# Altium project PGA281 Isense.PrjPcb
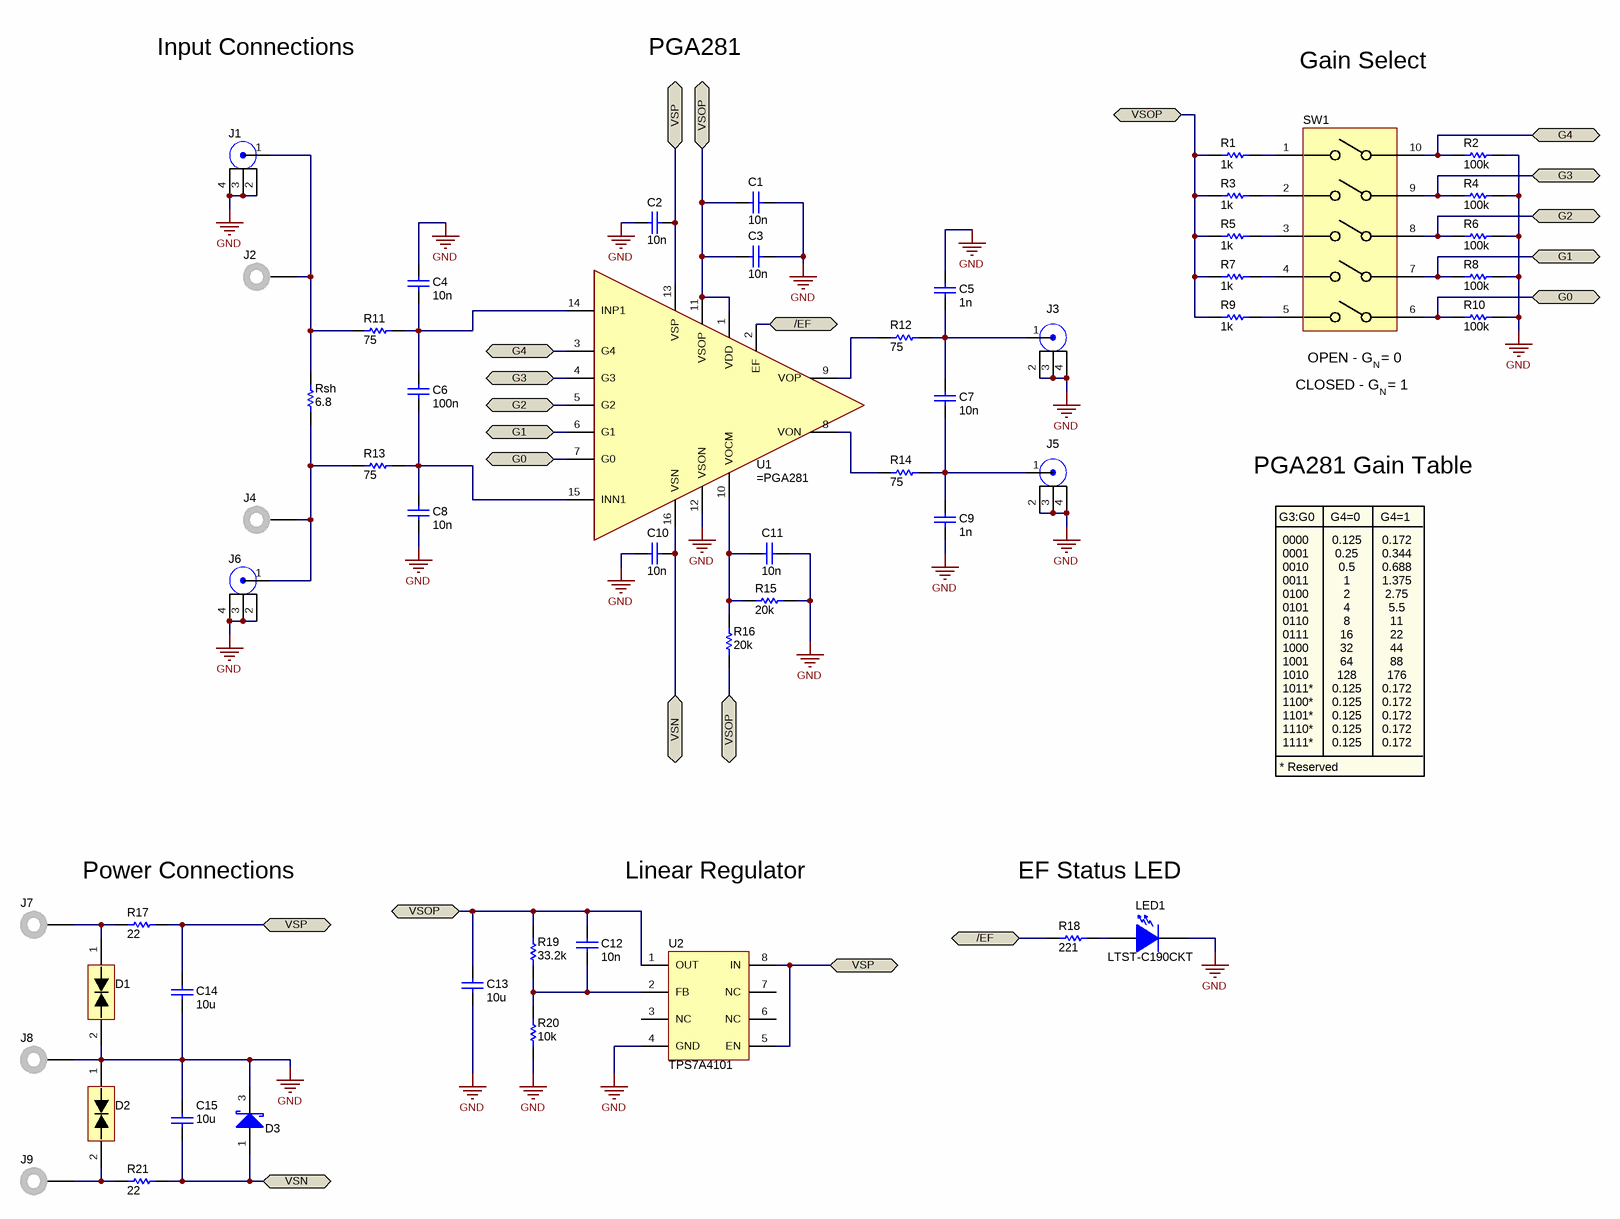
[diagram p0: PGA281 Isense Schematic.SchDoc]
CopyrightYear: 2012; PCB_Layout: Who did the Layout?; PCB_Rev: E1; PRJ_Customer: Public Release; PRJ_Engineer: Enter name of project lead; PRJ_Number: XX####; PRJ_Title: Change in menu Project|Project Options|Parameters; SCH_Rev: E1; TechSupport: http://www.ti.com/support
2 sheets, 58 parts. Net scope: flat (ports and power ports of the same name join across sheets).
Board file: PCB.PcbDoc
Sheets:
  PGA281 Isense Schematic.SchDoc
  Hardware_ANSI-B.SchDoc

## Sheet PGA281 Isense Schematic.SchDoc
size 431 x 279 mm; Date: Not shown in title block; ApprovedBy: Not shown in title block; CheckedBy: Not shown in title block; Author: Not shown in title block; CompanyName: Not shown in title block; Engineer: Not shown in title block; Organization: Not shown in title block; Address1: Not shown in title block; Address2: Not shown in title block; Address3: Not shown in title block; Address4: Not shown in title block; DocumentNumber: 1; Revision: Use project parameter SCH_Rev; SheetNumber: 1; SheetTotal: 1; PageSetup: Record=PageOptions|CenterHorizontal=True|CenterVertical=True|PrintScale=0.64|XCorrection=1.00|YCorrection=1.00|PrintKind=0|BorderSize=5000000|LeftOffset=0|BottomOffset=0|Orientation=2|PaperLength=1000|PaperWidth=1000|Scale=100|PaperSource=15|PrintQuality=600|MediaType=1|DitherType=10|PaperKind=Letter|PrintScaleMode=1

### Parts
C1  10n  [0603]
C2  10n  [0603]
C3  10n  [0603]
C4  10n  [0603]
C5  1n  [0603]
C6  100n  [0603]
C7  10n  [0603]
C8  10n  [0603]
C9  1n  [0603]
C10  10n  [0603]
C11  10n  [0603]
C12  10n  [0805]
C13  10u  [1206]
C14  10u  [1206]
C15  10u  [1206]
D1  SMBJ24CA  [SMB]  (value not drawn)
D2  SMBJ24CA  [SMB]  (value not drawn)
D3  BAS70-TP  [DBZ0003A_N]  (value not drawn)
J1  VIN+  [Right Angle BNC]  (value not drawn)
J2  I_IN+  [Johnson_108-0740-001]  (value not drawn)
J3  VOUT+  [Right Angle BNC]  (value not drawn)
J4  I_IN-  [Johnson_108-0740-001]  (value not drawn)
J5  VOUT-  [Right Angle BNC]  (value not drawn)
J6  VIN-  [Right Angle BNC]  (value not drawn)
J7  VSP  [Johnson_108-0740-001]  (value not drawn)
J8  GND  [Johnson_108-0740-001]  (value not drawn)
J9  VSN  [Johnson_108-0740-001]  (value not drawn)
LED1  LTST-C190CKT  [Diode_0603]
R1  value 1k  [0603]  (hidden comment: Used in BOM report)
R2  value 100k  [0603]  (hidden comment: Used in BOM report)
R3  value 1k  [0603]  (hidden comment: Used in BOM report)
R4  value 100k  [0603]  (hidden comment: Used in BOM report)
R5  value 1k  [0603]  (hidden comment: Used in BOM report)
R6  value 100k  [0603]  (hidden comment: Used in BOM report)
R7  value 1k  [0603]  (hidden comment: Used in BOM report)
R8  value 100k  [0603]  (hidden comment: Used in BOM report)
R9  value 1k  [0603]  (hidden comment: Used in BOM report)
R10  value 100k  [0603]  (hidden comment: Used in BOM report)
R11  value 75  [0805]  (hidden comment: Used in BOM report)
R12  value 75  [0805]  (hidden comment: Used in BOM report)
R13  value 75  [0805]  (hidden comment: Used in BOM report)
R14  value 75  [0805]  (hidden comment: Used in BOM report)
R15  value 20k  [0805]  (hidden comment: Used in BOM report)
R16  value 20k  [0805]  (hidden comment: Used in BOM report)
R17  value 22  [1206]  (hidden comment: Used in BOM report)
R18  value 221  [0805]  (hidden comment: Used in BOM report)
R19  value 33.2k  [0805]  (hidden comment: Used in BOM report)
R20  value 10k  [0805]  (hidden comment: Used in BOM report)
R21  value 22  [1206]  (hidden comment: Used in BOM report)
Rsh  value 6.8  [2512]  (hidden comment: Used in BOM report)
SW1  Used in BOM report  [A6S-5104-H]  (value not drawn)
U1  (no value)  [PW0016A_N]
U2  TPS7A4101  [dgk-8]

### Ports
/EF, G0, G1, G2, G3, G4, VSN, VSOP, VSP

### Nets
GND: C1.1 C2.2 C3.1 C4.1 C5.1 C8.2 C9.2 C10.1 C11.2 C13.2 C14.2 C15.1 D1.2 D2.1 D3.3 J1.2 J1.3 J1.4 J3.2 J3.3 J3.4 J5.2 J5.3 J5.4 J6.2 J6.3 J6.4 J8.1 LED1.2(K) R2.2 R4.2 R6.2 R8.2 R10.2 R15.1 R20.2 U1.12(VSON) U2.4(GND)
/EF: R18.1 U1.2(EF) ; port /EF
G0: R10.1 SW1.6 U1.7(G0) ; port G0
G1: R8.1 SW1.7 U1.6(G1) ; port G1
G2: R6.1 SW1.8 U1.5(G2) ; port G2
G3: R4.1 SW1.9 U1.4(G3) ; port G3
G4: R2.1 SW1.10 U1.3(G4) ; port G4
VSN: C10.2 C15.2 D3.1 R21.2 U1.16(VSN) ; port VSN
VSOP: C1.2 C3.2 C12.1 C13.1 R1.1 R3.1 R5.1 R7.1 R9.1 R16.1 R19.2 U1.1(VDD) U1.11(VSOP) U2.1(OUT) ; port VSOP
VSP: C2.1 C14.1 R17.2 U1.13(VSP) U2.5(EN) U2.8(IN) ; port VSP
NetC4_2: C4.2 C6.1 R11.2 U1.14(INP1)
NetC5_2: C5.2 C7.1 J3.1 R12.2
NetC6_2: C6.2 C8.1 R13.2 U1.15(INN1)
NetC7_2: C7.2 C9.1 J5.1 R14.2
NetC11_1: C11.1 R15.2 R16.2 U1.10(VOCM)
NetC12_2: C12.2 R19.1 R20.1 U2.2(FB)
NetD1_1: D1.1 J7.1 R17.1
NetD2_2: D2.2 J9.1 R21.1
NetJ1_1: J1.1 J2.1 R11.1 Rsh.2
NetJ4_1: J4.1 J6.1 R13.1 Rsh.1
NetLED1_1: LED1.1(A) R18.2
NetR1_2: R1.2 SW1.1
NetR3_2: R3.2 SW1.2
NetR5_2: R5.2 SW1.3
NetR7_2: R7.2 SW1.4
NetR9_2: R9.2 SW1.5
NetR12_1: R12.1 U1.9(VOP)
NetR14_1: R14.1 U1.8(VON)

Not connected (* = marked no-connect by the designer): D3 2; U2 3(NC) 6(NC) 7(NC)

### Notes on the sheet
- Input Connections
- PGA281
- Gain Select
- (near SW1) OPEN - G  = 0
- (near SW1) N
- CLOSED - G  = 1
- N
- PGA281 Gain Table
- 0000
- 0001
- 0010
- G3:G0
- G4=0
- 0.125
- 0.25
- 0.5
- G4=1
- 0.172
- 0.344
- 0.688
- 0011
- 0100
- 0101
- 0110
- 0111
- 1000
- 1
- 2
- 4
- 8
- 16
- 32
- 1.375
- 2.75
- 5.5
- 11
- 22
- 44
- 1001
- 1010
- 1011*
- 1100*
- 64
- 128
- 88
- 176
- 1101*
- 1110*
- 1111*
- * Reserved
- Power Connections
- Linear Regulator
- EF Status LED

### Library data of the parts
C1-C4 C6-C8 C10-C15 = Capacitor: CAP, CERM, xxxF, xxV, [TempCo], xx%, [PackageReference]; Manufacturer: Used in BOM report; Polarized: N; U/M: EA
C5 C9 = Capacitor: CAP, CERM, xxxF, xxV, [TempCo], xx%, [PackageReference]; Manufacturer: Used in BOM report; Polarized: N; Value: 10n; U/M: EA
D1 D2 = TVS_BI_SMB: Manufacturer: Used in BOM report; SymbolVersion: use current date i.e. 2008-05-20; SymbolCreator: Use a-id; CompType: Used in some BOM reports.  Useful for finding later.; U/M: EA, IN, or GM
D3 = BAS70-TP: Manufacturer: Used in BOM report; SymbolVersion: use current date i.e. 2008-05-20; SymbolCreator: Use a-id; CompType: Used in some BOM reports.  Useful for finding later.; U/M: EA, IN, or GM
J1 J3 J5 J6 = BNC Right Angle: Manufacturer: TE Connectivity; PartNumber: Used in BOM report; SymbolVersion: use current date i.e. 2008-05-20; SymbolCreator: Use LDAP id; CompType: Used in some BOM reports.  Useful for finding later.; U/M: EA, IN, or GM
J2 J4 J7-J9 = 108-0740-001: Standard Banana Jack, Uninsulated, 15A; Manufacturer: Emerson Network Power; SymbolCreator: a0412235; CompType: Connector; U/M: EA
LED1 = LED: LED, [Color], [MountType]; Manufacturer: Used in BOM report; U/M: EA
R1-R21 Rsh = Resistor: RES, xxx ohm, x%, xW, [PackageReference]; U/M: EA
SW1 = SWITCH_5xSPST: SymbolVersion: use current date i.e. 2008-05-20; SymbolCreator: Use a-id; CompType: Used in some BOM reports.  Useful for finding later.; U/M: EA, IN, or GM
U1 = PGA281: Manufacturer: Used in BOM report; SymbolVersion: use current date i.e. 2008-05-20; SymbolCreator: Use a-id; CompType: Used in some BOM reports.  Useful for finding later.; U/M: EA, IN, or GM
U2 = TPS7A4101: Manufacturer: Used in BOM report; SymbolVersion: use current date i.e. 2008-05-20; SymbolCreator: Use a-id; CompType: Used in some BOM reports.  Useful for finding later.; U/M: EA, IN, or GM

## Sheet Hardware_ANSI-B.SchDoc
size 431 x 279 mm; Date: Not shown in title block; ApprovedBy: Not shown in title block; CheckedBy: Not shown in title block; Author: Not shown in title block; CompanyName: Not shown in title block; Engineer: Not shown in title block; Organization: Not shown in title block; Address1: Not shown in title block; Address2: Not shown in title block; Address3: Not shown in title block; Address4: Not shown in title block; DocumentNumber: 1; Revision: Use project parameter SCH_Rev; SheetNumber: 1; SheetTotal: 1; PageSetup: Record=PageOptions|CenterHorizontal=True|CenterVertical=True|PrintScale=1.00|XCorrection=1.00|YCorrection=1.00|PrintKind=0|BorderSize=5000000|LeftOffset=0|BottomOffset=0|Orientation=2|PaperLength=1000|PaperWidth=1000|Scale=100|PaperSource=15|PrintQuality=600|MediaType=1|DitherType=10|PaperKind=Letter|PrintScaleMode=1
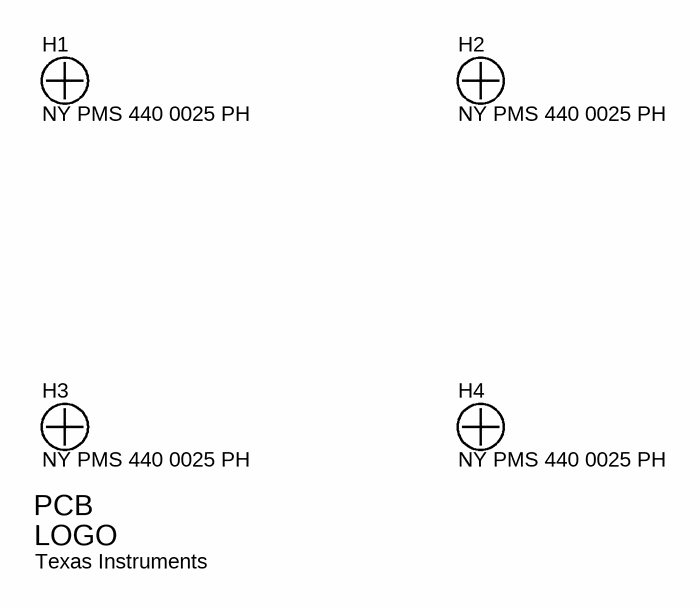
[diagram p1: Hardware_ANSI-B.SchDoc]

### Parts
H1  NY PMS 440 0025 PH  [NY PMS 440 0025 PH]
H2  NY PMS 440 0025 PH  [NY PMS 440 0025 PH]
H3  NY PMS 440 0025 PH  [NY PMS 440 0025 PH]
H4  NY PMS 440 0025 PH  [NY PMS 440 0025 PH]
Logo1  Texas Instruments  [TI_Stacked_Overlay_Medium]  (no BOM)

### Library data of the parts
H1-H4 = NY PMS 440 0025 PH: Machine Screw, Round, #4-40 x 1/4, Nylon, Philips panhead; Manufacturer: B&F Fastener Supply; CompType: Hardware; SymbolCreator: codlsc; U/M: EA
Logo1 = TI_Logo: Texas Instrument Corporate Signature; SymbolCreator: codlsc

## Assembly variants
001: all parts fitted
